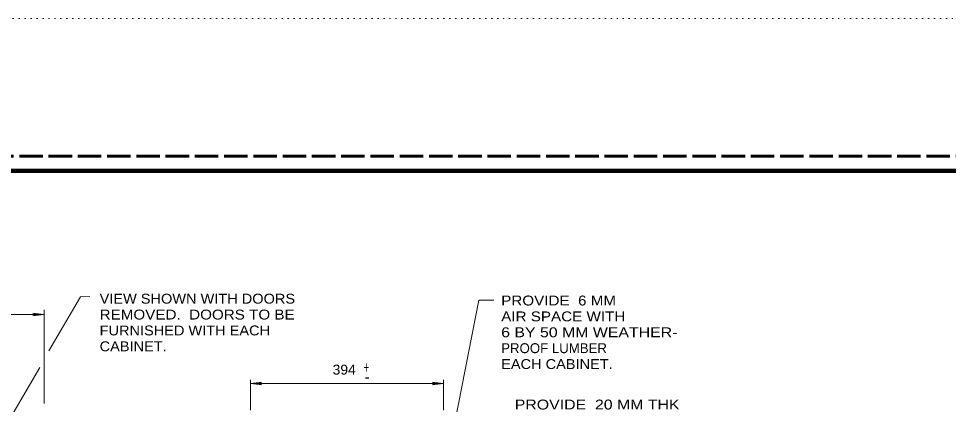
# Model space of a CAD drawing. Extents: x 312583 to 312854, y 144419 to 144597.
# Drawn here: x 312696.9 to 312768.4, y 144567.2 to 144596.8 of the extents above; entities that cross this region are included whole.
import ezdxf
from ezdxf.enums import TextEntityAlignment as Align

# ---------------------------------------------------------------- set-up
doc = ezdxf.new("R2010")
doc.units = 0
doc.header["$LTSCALE"] = 0.3
doc.linetypes.add('DOTTED', pattern=[1.5, 0.3, -1.2])
doc.linetypes.add('LONG_DASHED', pattern=[7.5, 6, -1.5])
doc.layers.add('1', color=7, linetype='Continuous', lineweight=25)
doc.layers.add('2', color=7, linetype='Continuous', lineweight=13)

msp = doc.modelspace()

# ---------------------------------------------------------------- linework, layer by layer
at = {"layer": '1', "linetype": 'DOTTED', "lineweight": 13}
msp.add_line((312601.2, 144596.7846), (312853.5, 144596.7846), dxfattribs=at)
at = {"layer": '1', "linetype": 'LONG_DASHED', "lineweight": 60}
msp.add_line((312851.75, 144586.2246), (312583.526, 144586.2246), dxfattribs=at)
at = {"layer": '1', "lineweight": 158}
msp.add_line((312616.5, 144585.0846), (312849, 144585.0846), dxfattribs=at)
at = {"layer": '2'}
for p, q in [((312698.8655, 144567.209), (312698.8655, 144574.408)), ((312669.7551, 144574.0553), (312698.8655, 144574.0553)), ((312697.9991, 144574.1626), (312698.2751, 144574.0553)), ((312698.8655, 144574.0553), (312697.9991, 144574.1626)), ((312697.9991, 144573.948), (312698.2751, 144574.0553)), ((312698.8655, 144574.0553), (312697.9991, 144573.948)), ((312698.5322, 144569.9951), (312695.9445, 144565.5683)), ((312714.7182, 144566.7106), (312714.7182, 144569.0336)), ((312714.7182, 144568.7576), (312715.5845, 144568.865)), ((312714.7182, 144568.7576), (312729.5685, 144568.7576)), ((312714.7182, 144568.7576), (312715.5845, 144568.6503)), ((312715.5845, 144568.865), (312715.3085, 144568.7576)), ((312715.5845, 144568.6503), (312715.3085, 144568.7576)), ((312728.7022, 144568.865), (312728.9782, 144568.7576)), ((312729.5685, 144568.7576), (312728.7022, 144568.865)), ((312728.7022, 144568.6503), (312728.9782, 144568.7576)), ((312729.5685, 144568.7576), (312728.7022, 144568.6503)), ((312729.5685, 144566.7106), (312729.5685, 144569.0336))]:
    msp.add_line(p, q, dxfattribs=at)
for points in [[(312702.3755, 144575.4293), (312701.644, 144575.423), (312699.205, 144571.2574)], [(312733.4325, 144575.1578), (312732.2825, 144575.1578), (312729.1315, 144559.113)]]:
    msp.add_lwpolyline(points, dxfattribs=at)

# ---------------------------------------------------------------- texts
for s, width, p in [('VIEW SHOWN WITH DOORS', 1.1, (312703.1222, 144574.8919)), ('PROVIDE  6 MM', 1.15, (312733.9999, 144574.7504)), ('REMOVED.  DOORS TO BE', 1.15, (312703.1222, 144573.6719)), ('AIR SPACE WITH', 1.15, (312733.9999, 144573.5304)), ('FURNISHED WITH EACH', 1.1, (312703.1222, 144572.4519)), ('6 BY 50 MM WEATHER-', 1.2, (312733.9999, 144572.3104)), ('CABINET.', 1.1, (312703.1222, 144571.2319)), ('394', 1.05, (312721.0384, 144569.4448)), ('EACH CABINET.', 1.1, (312733.9999, 144569.8704)), ('PROVIDE  20 MM THK', 1.2, (312735.0431, 144566.7604))]:
    msp.add_text(s, height=0.76, dxfattribs=dict(at, width=width)).set_placement(p)
msp.add_text('PROOF LUMBER', height=0.76, dxfattribs=at).set_placement((312733.9999, 144571.0904))
at = {"layer": '2', "width": 0.6}
msp.add_text('+', height=0.92, dxfattribs=at).set_placement((312723.6192, 144569.5396), align=Align.CENTER)
at = {"layer": '2'}
msp.add_text('-', height=0.92, dxfattribs=at).set_placement((312723.6959, 144568.8266), align=Align.CENTER)

doc.saveas('drawing.dxf')
